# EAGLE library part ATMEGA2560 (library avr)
MICROCONTROLLER 256 kBytes FLASH 8 kBytes SRAM 4 kBytes EEPROM QUAD USART 16-channel 10 bit ADC
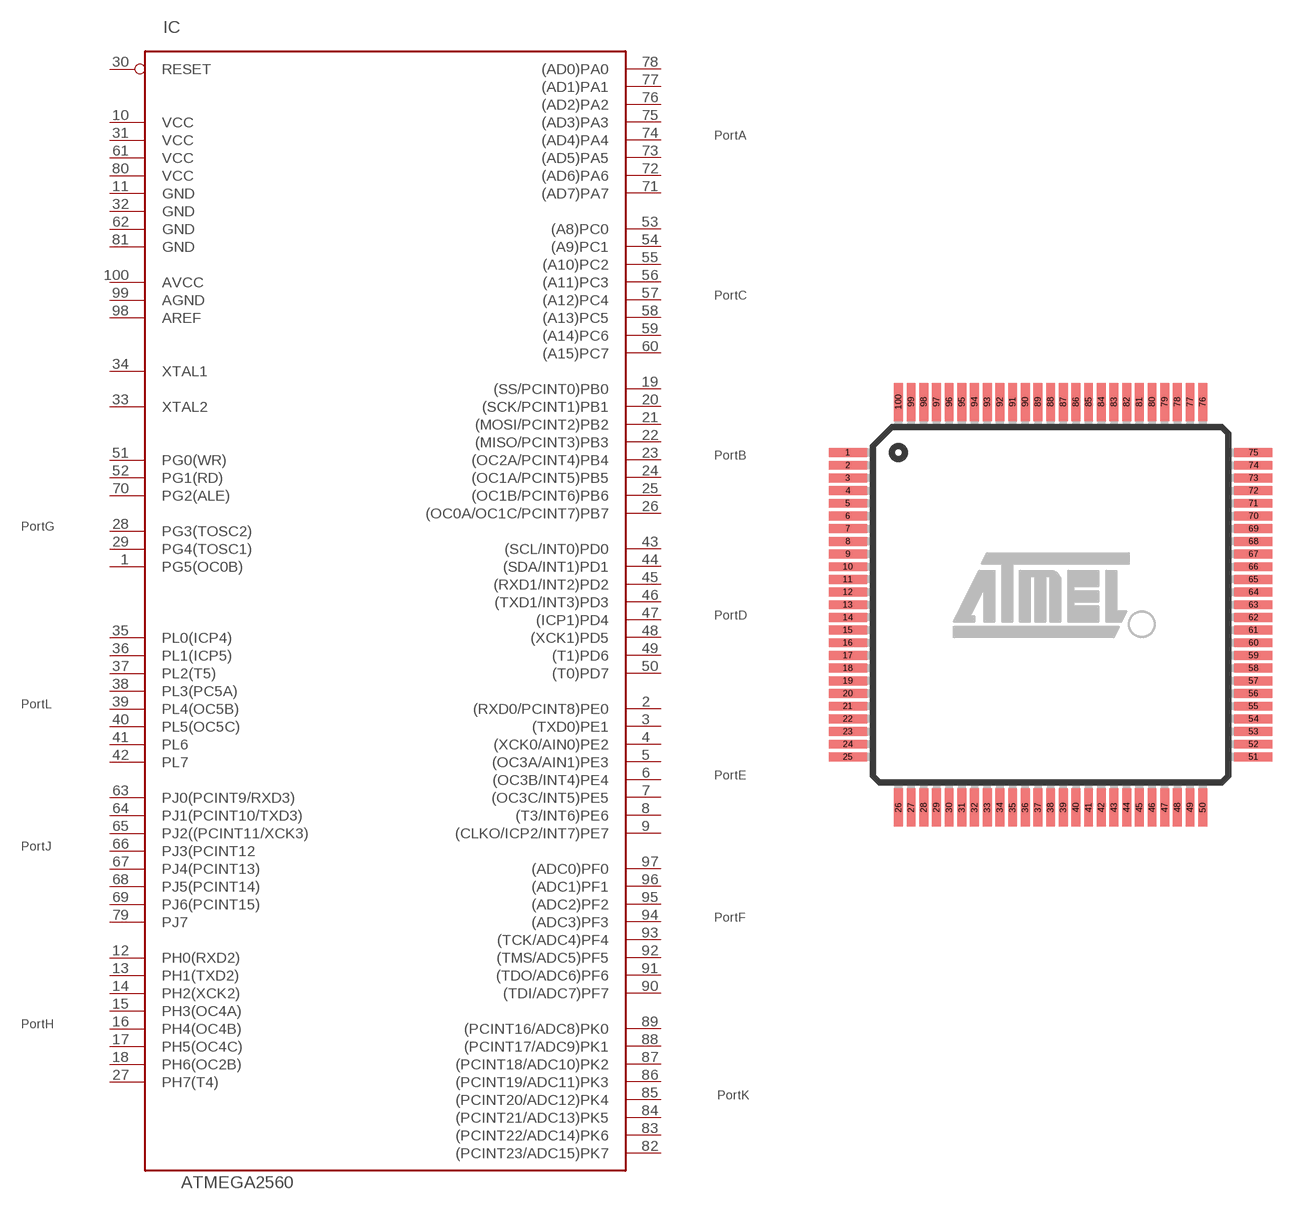
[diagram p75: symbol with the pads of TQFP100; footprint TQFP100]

Designator prefix IC

## ATMEGA2560-16A, ATMEGA2560V-8A  [TQFP100]
1  PG5(OC0B)
2  (RXD0/PCINT8)PE0
3  (TXD0)PE1
4  (XCK0/AIN0)PE2
5  (OC3A/AIN1)PE3
6  (OC3B/INT4)PE4
7  (OC3C/INT5)PE5
8  (T3/INT6)PE6
9  (CLKO/ICP2/INT7)PE7
10  VCC  pwr
11  GND  pwr
12  PH0(RXD2)
13  PH1(TXD2)
14  PH2(XCK2)
15  PH3(OC4A)
16  PH4(OC4B)
17  PH5(OC4C)
18  PH6(OC2B)
19  (SS/PCINT0)PB0
20  (SCK/PCINT1)PB1
21  (MOSI/PCINT2)PB2
22  (MISO/PCINT3)PB3
23  (OC2A/PCINT4)PB4
24  (OC1A/PCINT5)PB5
25  (OC1B/PCINT6)PB6
26  (OC0A/OC1C/PCINT7)PB7
27  PH7(T4)
28  PG3(TOSC2)
29  PG4(TOSC1)
30  RESET  in
31  VCC  pwr
32  GND  pwr
33  XTAL2  in
34  XTAL1  in
35  PL0(ICP4)
36  PL1(ICP5)
37  PL2(T5)
38  PL3(PC5A)
39  PL4(OC5B)
40  PL5(OC5C)
41  PL6
42  PL7
43  (SCL/INT0)PD0
44  (SDA/INT1)PD1
45  (RXD1/INT2)PD2
46  (TXD1/INT3)PD3
47  (ICP1)PD4
48  (XCK1)PD5
49  (T1)PD6
50  (T0)PD7
51  PG0(WR)
52  PG1(RD)
53  (A8)PC0
54  (A9)PC1
55  (A10)PC2
56  (A11)PC3
57  (A12)PC4
58  (A13)PC5
59  (A14)PC6
60  (A15)PC7
61  VCC  pwr
62  GND  pwr
63  PJ0(PCINT9/RXD3)
64  PJ1(PCINT10/TXD3)
65  PJ2((PCINT11/XCK3)
66  PJ3(PCINT12
67  PJ4(PCINT13)
68  PJ5(PCINT14)
69  PJ6(PCINT15)
70  PG2(ALE)
71  (AD7)PA7
72  (AD6)PA6
73  (AD5)PA5
74  (AD4)PA4
75  (AD3)PA3
76  (AD2)PA2
77  (AD1)PA1
78  (AD0)PA0
79  PJ7
80  VCC  pwr
81  GND  pwr
82  (PCINT23/ADC15)PK7
83  (PCINT22/ADC14)PK6
84  (PCINT21/ADC13)PK5
85  (PCINT20/ADC12)PK4
86  (PCINT19/ADC11)PK3
87  (PCINT18/ADC10)PK2
88  (PCINT17/ADC9)PK1
89  (PCINT16/ADC8)PK0
90  (TDI/ADC7)PF7
91  (TDO/ADC6)PF6
92  (TMS/ADC5)PF5
93  (TCK/ADC4)PF4
94  (ADC3)PF3
95  (ADC2)PF2
96  (ADC1)PF1
97  (ADC0)PF0
98  AREF  pwr
99  AGND  pwr
100  AVCC  pwr

## Footprint TQFP100 (pad centres in mm)
100-lead Thin Quad Flat Pack Package Outline
smd 1.5 x 0.35: 1 -8,6; 2 -8,5.5; 3 -8,5; 4 -8,4.5; 5 -8,4; 6 -8,3.5; 7 -8,3; 8 -8,2.5; 9 -8,2; 10 -8,1.5; 11 -8,1; 12 -8,0.5; 13 -8,0; 14 -8,-0.5; 15 -8,-1; 16 -8,-1.5; 17 -8,-2; 18 -8,-2.5; 19 -8,-3; 20 -8,-3.5; 21 -8,-4; 22 -8,-4.5; 23 -8,-5; 24 -8,-5.5; 25 -8,-6; 51 8,-6; 52 8,-5.5; 53 8,-5; 54 8,-4.5; 55 8,-4; 56 8,-3.5; 57 8,-3; 58 8,-2.5; 59 8,-2; 60 8,-1.5; 61 8,-1; 62 8,-0.5; 63 8,0; 64 8,0.5; 65 8,1; 66 8,1.5; 67 8,2; 68 8,2.5; 69 8,3; 70 8,3.5; 71 8,4; 72 8,4.5; 73 8,5; 74 8,5.5; 75 8,6
smd 0.35 x 1.5: 26 -6,-8; 27 -5.5,-8; 28 -5,-8; 29 -4.5,-8; 30 -4,-8; 31 -3.5,-8; 32 -3,-8; 33 -2.5,-8; 34 -2,-8; 35 -1.5,-8; 36 -1,-8; 37 -0.5,-8; 38 0,-8; 39 0.5,-8; 40 1,-8; 41 1.5,-8; 42 2,-8; 43 2.5,-8; 44 3,-8; 45 3.5,-8; 46 4,-8; 47 4.5,-8; 48 5,-8; 49 5.5,-8; 50 6,-8; 76 6,8; 77 5.5,8; 78 5,8; 79 4.5,8; 80 4,8; 81 3.5,8; 82 3,8; 83 2.5,8; 84 2,8; 85 1.5,8; 86 1,8; 87 0.5,8; 88 0,8; 89 -0.5,8; 90 -1,8; 91 -1.5,8; 92 -2,8; 93 -2.5,8; 94 -3,8; 95 -3.5,8; 96 -4,8; 97 -4.5,8; 98 -5,8; 99 -5.5,8; 100 -6,8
